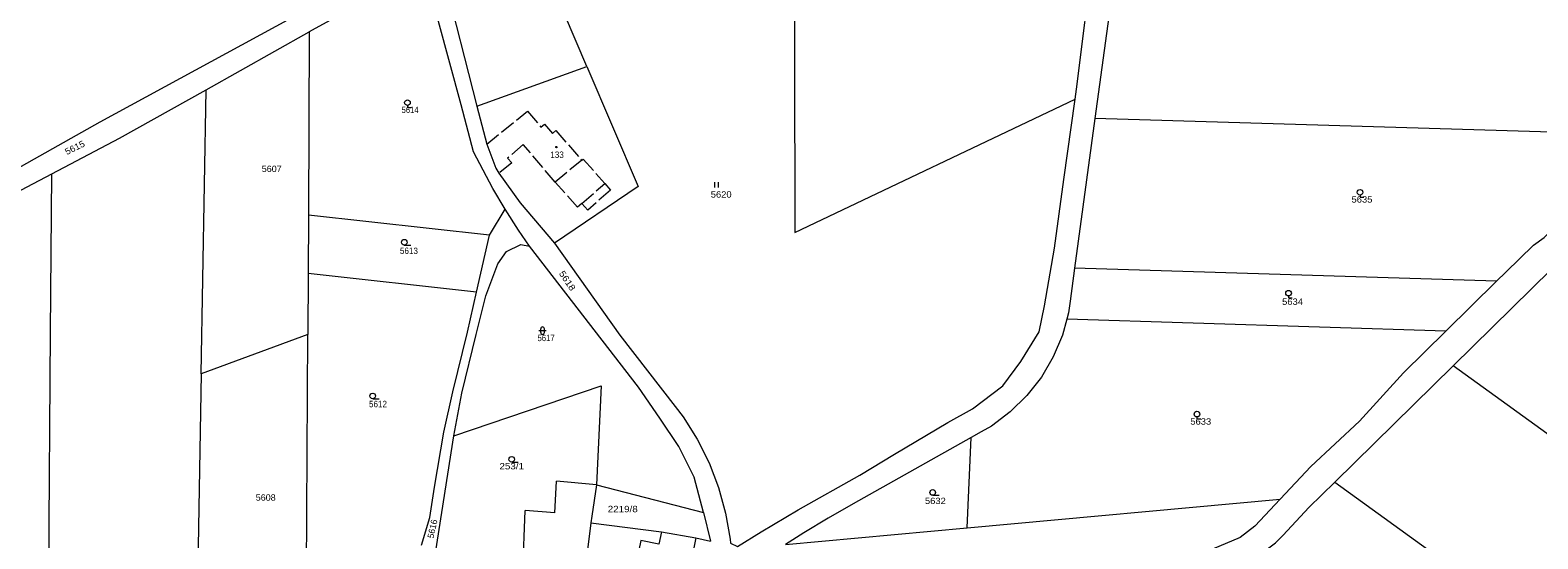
# Model space of a CAD drawing. Extents: x -590528 to -586543, y -1119609 to -1116685.
# Drawn here: x -588764.7 to -588363.1, y -1117852.7 to -1117717.3 of the extents above; entities that cross this region are included whole.
import ezdxf
from ezdxf.enums import TextEntityAlignment as Align

# ---------------------------------------------------------------- set-up
doc = ezdxf.new("R2010")
doc.units = 0
doc.header["$LTSCALE"] = 0.68
doc.linetypes.add('LONG_DASHED', pattern=[7.5, 6, -1.5])
for name, color, linetype, lineweight in [('1', 7, 'Continuous', 13), ('2', 7, 'LONG_DASHED', 13), ('3', 7, 'Continuous', 13), ('6', 7, 'Continuous', 13)]:
    doc.layers.add(name, color=color, linetype=linetype, lineweight=lineweight)

msp = doc.modelspace()

# ---------------------------------------------------------------- linework, layer by layer
at = {"layer": '1'}
for p, q in [((-588385.65, -1117806.64), (-588308.28, -1117730.61)), ((-588746.16, -1117741.76), (-588839.01, -1117793.97)), ((-588481.05, -1117740.85), (-588486.47, -1117780.62)), ((-588759.25, -1117797.78), (-588758.92, -1117755.56)), ((-588690.6, -1117766.52), (-588690.68, -1117782.07)), ((-588374.08, -1117784.15), (-588486.47, -1117780.62)), ((-588387.6, -1117797.43), (-588488.57, -1117794.26)), ((-588760.63, -1117974.34), (-588759.25, -1117797.78)), ((-588691.12, -1117874.52), (-588690.76, -1117798.31)), ((-588226.58, -1117921.5), (-588385.65, -1117806.64)), ((-588534.47, -1117830.19), (-588520.28, -1117821.78)), ((-588656.66, -1117855.95), (-588651.81, -1117825.28)), ((-588515.09, -1117849.79), (-588514.05, -1117825.76)), ((-588624.91, -1117845.83), (-588624.49, -1117837.34)), ((-588613.86, -1117838.35), (-588624.49, -1117837.34)), ((-588613.86, -1117838.35), (-588615.1, -1117846.71)), ((-588613.86, -1117838.35), (-588585.36, -1117845.73)), ((-588417.18, -1117837.61), (-588270.98, -1117943.18)), ((-588633.72, -1117867.6), (-588632.84, -1117845.2)), ((-588624.91, -1117845.83), (-588632.84, -1117845.2)), ((-588585.36, -1117845.73), (-588583.47, -1117853.36)), ((-588615.32, -1117848.49), (-588596.48, -1117850.88)), ((-588587.41, -1117852.47), (-588583.47, -1117853.36))]:
    msp.add_line(p, q, dxfattribs=at)
for points in [[(-588486.35, -1117735.66), (-588485.97, -1117733.01), (-588481.45, -1117696.91), (-588476.78, -1117659.71), (-588475.01, -1117646.52), (-588472.27, -1117633.74)], [(-588466.77, -1117646.73), (-588471.46, -1117673.56), (-588472.39, -1117679.02), (-588473.26, -1117684.49), (-588474.09, -1117689.96), (-588474.86, -1117695.45), (-588481.05, -1117740.85)], [(-588561.21, -1117676.04), (-588560.96, -1117771.2), (-588486.35, -1117735.66)], [(-588631.65, -1117691.14), (-588652.8, -1117699.46), (-588654.35, -1117701.63), (-588654.54, -1117703.04), (-588645.67, -1117737.56), (-588643.08, -1117747.63), (-588640.63, -1117754.02)], [(-588645.67, -1117737.56), (-588616.38, -1117726.97), (-588631.65, -1117691.14)], [(-588661.91, -1117698.38), (-588664.54, -1117699.61), (-588676.52, -1117705.2), (-588691.07, -1117711.89), (-588746.16, -1117741.76)], [(-588662.62, -1117704.65), (-588666.31, -1117706.13), (-588672.27, -1117708.63), (-588678.15, -1117711.33), (-588683.93, -1117714.22), (-588689.61, -1117717.29), (-588690.36, -1117717.71), (-588690.6, -1117766.52)], [(-588641.48, -1117759.48), (-588646.61, -1117749.7), (-588649.93, -1117737.19), (-588655.92, -1117715.01), (-588658.71, -1117708.06), (-588662.62, -1117704.65)], [(-588719.16, -1117808.83), (-588717.85, -1117733.14), (-588690.36, -1117717.71)], [(-588616.38, -1117726.97), (-588602.77, -1117758.9), (-588625.06, -1117774.05)], [(-588758.92, -1117755.56), (-588740.89, -1117746.08), (-588717.85, -1117733.14)], [(-588491.81, -1117775.38), (-588489.37, -1117757.05), (-588486.35, -1117735.66)], [(-588371.64, -1117781.76), (-588364.25, -1117774.53), (-588361.36, -1117772.5), (-588355.73, -1117766.93), (-588349.41, -1117764.74), (-588329.68, -1117745.35), (-588481.05, -1117740.85)], [(-588796.35, -1117775.23), (-588785.3, -1117769.43), (-588758.92, -1117755.56)], [(-588640.63, -1117754.02), (-588639.81, -1117755.41), (-588634.21, -1117763.25), (-588625.06, -1117774.05)], [(-588642.33, -1117771.86), (-588638.13, -1117764.92), (-588641.48, -1117759.48)], [(-588645.81, -1117787.01), (-588642.33, -1117771.86), (-588690.6, -1117766.52)], [(-588640.16, -1117779.53), (-588637.81, -1117776.22), (-588633.97, -1117774.32), (-588631.71, -1117774.82), (-588634.65, -1117770.56), (-588638.13, -1117764.92)], [(-588591.87, -1117828.17), (-588596.95, -1117820.61), (-588602.62, -1117812.32), (-588631.71, -1117774.82)], [(-588625.06, -1117774.05), (-588607.64, -1117798.51), (-588592.92, -1117817.49), (-588590.76, -1117820.27), (-588587, -1117826.23)], [(-588520.28, -1117821.78), (-588513.67, -1117818.09), (-588505.59, -1117811.99), (-588500.77, -1117805.5), (-588495.88, -1117797.59), (-588494.47, -1117790.72), (-588491.81, -1117775.38)], [(-588651.81, -1117825.28), (-588649.73, -1117813.94), (-588645.89, -1117798.36), (-588643.28, -1117788.04), (-588640.16, -1117779.53)], [(-588645.81, -1117787.01), (-588690.68, -1117782.07), (-588690.76, -1117798.31)], [(-588486.47, -1117780.62), (-588487.67, -1117789.43), (-588488.1, -1117792.52), (-588488.57, -1117794.26)], [(-588398.89, -1117808.51), (-588387.6, -1117797.43), (-588374.08, -1117784.15), (-588371.64, -1117781.76)], [(-588654.49, -1117824.36), (-588652.1, -1117813.55), (-588648.24, -1117797.73), (-588645.81, -1117787.01)], [(-588488.57, -1117794.26), (-588489.74, -1117798.53), (-588492.17, -1117804.28), (-588495.33, -1117809.66), (-588499.16, -1117814.58), (-588503.62, -1117818.95), (-588508.6, -1117822.69), (-588511.32, -1117824.22), (-588514.05, -1117825.76)], [(-588690.76, -1117798.31), (-588719.16, -1117808.83), (-588720.48, -1117885.36), (-588721.77, -1117959.96), (-588700.15, -1117951.11)], [(-588436.89, -1117856.73), (-588432.98, -1117853.83), (-588430.89, -1117851.77), (-588424.08, -1117844.39), (-588417.18, -1117837.61), (-588385.65, -1117806.64)], [(-588651.81, -1117825.28), (-588612.56, -1117811.98), (-588613.86, -1117838.35)], [(-588515.09, -1117849.79), (-588431.73, -1117842.18), (-588423.54, -1117833.48), (-588410.61, -1117821.4), (-588398.89, -1117808.51)], [(-588660.45, -1117854.43), (-588658.26, -1117847.01), (-588656.96, -1117839), (-588654.49, -1117824.36)], [(-588585.36, -1117845.73), (-588587.85, -1117836.34), (-588591.87, -1117828.17)], [(-588587, -1117826.23), (-588583.85, -1117832.52), (-588581.32, -1117839.09), (-588579.44, -1117845.88)], [(-588514.05, -1117825.76), (-588545.49, -1117843.44), (-588552.09, -1117847.24), (-588558.61, -1117851.17), (-588563.45, -1117854.2), (-588515.09, -1117849.79)], [(-588579.44, -1117845.88), (-588578.22, -1117852.82), (-588578.15, -1117853.87), (-588576.25, -1117854.8), (-588570, -1117850.87), (-588560.11, -1117845.04), (-588543.67, -1117835.8), (-588534.47, -1117830.19)], [(-588431.73, -1117842.18), (-588438.44, -1117849.32), (-588442.39, -1117852.33), (-588453.1, -1117856.88), (-588458.84, -1117857.49), (-588479.87, -1117859.78), (-588503.81, -1117862.19), (-588512.2, -1117862.93), (-588516.4, -1117863.24)], [(-588615.1, -1117846.71), (-588615.32, -1117848.49), (-588616.57, -1117858.49)], [(-588596.48, -1117850.88), (-588597.22, -1117854.15), (-588602.02, -1117853.2), (-588602.52, -1117855.7), (-588602.91, -1117857.66), (-588600.26, -1117858.18), (-588600.92, -1117861.52), (-588597.98, -1117862.1), (-588598.12, -1117862.83)], [(-588596.48, -1117850.88), (-588587.41, -1117852.47), (-588589.41, -1117862.58)]]:
    msp.add_lwpolyline(points, dxfattribs=at)
at = {"layer": '2'}
for p, q in [((-588617.76, -1117751.92), (-588624.82, -1117757.73)), ((-588617.71, -1117763.45), (-588611.64, -1117758.1))]:
    msp.add_line(p, q, dxfattribs=at)
msp.add_lwpolyline([(-588643.08, -1117747.63), (-588632.18, -1117738.84), (-588628.62, -1117743.08), (-588627.7, -1117742.3), (-588625.59, -1117744.77), (-588624.7, -1117744.01), (-588617.76, -1117751.92), (-588617.38, -1117751.63), (-588611.64, -1117758.1), (-588610.11, -1117759.87), (-588616.16, -1117765.18), (-588617.71, -1117763.45), (-588618.9, -1117764.46), (-588624.82, -1117757.73), (-588633.36, -1117747.74), (-588637.5, -1117751.38), (-588636.4, -1117752.63), (-588639.81, -1117755.41)], dxfattribs=at)
at = {"layer": '6'}
for p, q in [((-588582.31, -1117759.23), (-588582.31, -1117757.73)), ((-588581.31, -1117759.23), (-588581.31, -1117757.73)), ((-588665.03, -1117774.51), (-588663.28, -1117774.51)), ((-588629.2, -1117797.29), (-588627.2, -1117797.29)), ((-588628.7, -1117797.79), (-588628.7, -1117796.79)), ((-588627.7, -1117797.79), (-588627.7, -1117796.79)), ((-588673.45, -1117815.43), (-588671.7, -1117815.43)), ((-588636.42, -1117832.29), (-588634.67, -1117832.29)), ((-588524.28, -1117841.13), (-588522.53, -1117841.13))]:
    msp.add_line(p, q, dxfattribs=at)
for points in [[(-588664.2, -1117737.35), (-588664.2, -1117737.85), (-588663.2, -1117737.85)], [(-588410.43, -1117761.22), (-588410.43, -1117761.72), (-588409.43, -1117761.72)], [(-588429.48, -1117788.07), (-588429.48, -1117788.57), (-588428.48, -1117788.57)], [(-588453.87, -1117820.27), (-588453.87, -1117820.77), (-588452.87, -1117820.77)]]:
    msp.add_lwpolyline(points, dxfattribs=at)
for centre, radius in [((-588664.2, -1117736.6), 0.75), ((-588624.5002, -1117748.4204), 0.175), ((-588410.43, -1117760.47), 0.75), ((-588665.03, -1117773.76), 0.75), ((-588429.48, -1117787.32), 0.75), ((-588673.45, -1117814.68), 0.75), ((-588453.87, -1117819.52), 0.75), ((-588636.42, -1117831.54), 0.75), ((-588524.28, -1117840.38), 0.75)]:
    msp.add_circle(centre, radius, dxfattribs=at)
for centre, start, end in [((-588628.2, -1117796.79), 0, 179.99999), ((-588628.2, -1117797.79), 179.99999, 359.99999)]:
    msp.add_arc(centre, 0.5, start, end, dxfattribs=at)

# ---------------------------------------------------------------- texts
at = {"layer": '3'}
for s, width, p in [('5614', 0.9, (-588665.763, -1117739.35)), ('133', 0.95, (-588626.147, -1117751.31)), ('5607', 1.05, (-588703.013, -1117755.08)), ('5620', 1.1, (-588583.403, -1117761.88)), ('5635', 1.1, (-588412.703, -1117763.2)), ('5613', 0.95, (-588666.203, -1117776.88)), ('5634', 1.1, (-588431.193, -1117790.43)), ('5617', 0.9, (-588629.533, -1117800.09)), ('5612', 0.95, (-588674.443, -1117817.68)), ('5633', 1.1, (-588455.653, -1117822.33)), ('5608', 1.05, (-588704.613, -1117842.58)), ('5632', 1.1, (-588526.343, -1117843.47))]:
    msp.add_text(s, height=1.7, dxfattribs=dict(at, width=width)).set_placement(p)
for s, rotation, width, p in [('5615', 26.127, 1.1, (-588754.927, -1117750.565)), ('5618', 303.897, 1.15, (-588623.928, -1117782.067))]:
    msp.add_text(s, height=1.7, rotation=rotation, dxfattribs=dict(at, width=width)).set_placement(p)
at = {"layer": '3', "width": 1.15}
for s, p in [('253/1', (-588636.4205, -1117834.24)), ('2219/8', (-588606.8405, -1117845.64))]:
    msp.add_text(s, height=1.7, dxfattribs=at).set_placement(p, align=Align.CENTER)
at = {"layer": '3'}
msp.add_text('5616', height=1.7, rotation=77.75, dxfattribs=at).set_placement((-588657.25, -1117852.718))

doc.saveas('drawing.dxf')
